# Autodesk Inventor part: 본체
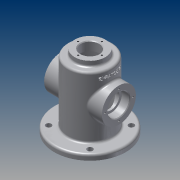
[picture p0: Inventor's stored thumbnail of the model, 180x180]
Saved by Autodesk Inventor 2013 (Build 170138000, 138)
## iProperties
Created: 2014-12
Part Number: 본체
Material: 알루미늄 6061
Document SubType Name: Modeling
Designer: CAD-B28
Density: 2.71 g/cm^3
Mass: 478.821 g
Surface Area: 609.662 cm^2
Volume: 176.687 cm^3
Author: CAD-B28
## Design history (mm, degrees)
sketch "스케치1"
  geometry: C1 r 32.5 at (0, 0); 1 further point
  constraints: 1 centre point, 1 coincident
  dimensions: "d0" = 65 diameter of C1
extrude "돌출1" new body sketch "스케치1" distance "d1" = 43; taper "d3" = 0 deg; dims "d2" = 55, "d4" = 0
sketch "스케치2"
  geometry: C1 r 32.5 at (0, 0) reference; C2 r 52.5 at (0, 0)
  constraints: 1 centre point, 1 coincident
  dimensions: "d5" = 105 diameter of C2
extrude "돌출2" join sketch "스케치2" distance "d6" = 8; taper "d7" = 0 deg
sketch "스케치3"
  geometry: C1 r 52.5 at (0, 0) reference; C2 r 27.5 at (0, 0)
  constraints: 1 centre point, 1 coincident
  dimensions: "d8" = 55 diameter of C2
extrude "돌출3" cut sketch "스케치3" distance "d9" = 93; taper "d10" = 0 deg
sketch "스케치4"
  geometry: L1 (-42.5, 0)-(54.519, 0) reference; L2 (-42.5, 0)-(-42.5, 25); L3 (-42.5, 25)-(42.5, 25); L4 (42.5, 25)-(42.5, 0); L5 (-32.5, -47)-(-32.5, 43) reference; L6 (32.5, -47)-(32.5, 43) reference; 1 further point
  constraints: 8 end point, 3 perpendicular, 2 horizontal, 1 point on line
  dimensions: "d11" = 50 diameter of L3 L1; "d13" = 10 distance between parallel lines of L5 L2; "d14" = 10 distance between parallel lines of L4 L6
revolve "회전1" sketch "스케치4" stored, may be unused: angle "d15" = 90 deg
sketch "스케치5"
  geometry: L1 (-42.66, 0)-(42.5, 0) reference; L2 (-42.66, 0)-(-42.66, 16); L3 (-42.66, 16)-(-30.66, 16); L4 (-30.66, 16)-(-30.66, 12.5); L5 (-30.66, 12.5)-(30.5, 12.5); L6 (30.5, 12.5)-(30.5, 16); L7 (30.5, 16)-(42.5, 16); L8 (42.5, 16)-(42.5, 0); L9 (42.5, -25)-(42.5, 25) reference; 2 further points
  constraints: 16 end point, 4 parallel, 2 horizontal, 2 perpendicular, 1 collinear, 1 midpoint, 1 point on line
  dimensions: "d16" = 12 distance of L2.end L3.end; "d18" = 12 distance of L6.end L7.end; "d19" = 32 diameter of L7 L1; "d21" = 32 diameter of L3 L1; "d22" = 25 diameter of L5 L1
revolve "회전2" sketch "스케치5" stored, may be unused: angle "d23" = 90 deg
extrude "돌출4" cut sketch "스케치3" distance "d24" = 93; taper "d25" = 0 deg
sketch "스케치6"
  geometry: C1 r 32.5 at (0, 0) reference; C2 r 22.5 at (0, 0)
  constraints: 1 centre point, 1 coincident
  dimensions: "d26" = 45 diameter of C2
extrude "돌출5" join sketch "스케치6" distance "d27" = 8; taper "d28" = 0 deg
sketch "스케치7"
  geometry: C1 r 22.5 at (0, 0) reference; C2 r 13.5 at (0, 0)
  constraints: 1 centre point, 1 coincident
  dimensions: "d29" = 27 diameter of C2
extrude "돌출6" cut sketch "스케치7" stored distance "d30" = 8; taper "d31" = 0 deg
sketch "스케치8" dims "d32" = 41
  geometry: L1 (0, 0)-(25, 0); 2 further points
  constraints: 2 end point, 2 horizontal alignment, 1 coincident, 1 horizontal, 1 point on line, 3 other
hole "구멍1" sketch "스케치8" at (20.5, 0) diameter "d33" = 2.459; stored, may be unused: countersink angle "d37" = 90 deg, drill point angle "d39" = 118 deg; dims "d34" = 6, "d35" = 4, "d36" = 2, "d38" = 8
sketch "스케치9" dims "d43" = 35
  geometry: L1 (0, 0)-(0, 20.281); C1 r 22.5 at (0, 0) reference; 1 further point
  constraints: 2 end point, 1 coincident, 1 point on line, 1 vertical, 1 vertical alignment, 2 other
hole "구멍2" sketch "스케치9" at (0, 17.5) diameter "d44" = 2.459; stored, may be unused: countersink angle "d48" = 90 deg, drill point angle "d50" = 118 deg; dims "d45" = 6, "d46" = 4, "d47" = 2, "d49" = 8
chamfer "모따기1" distance "d54" = 1; stored, may be unused: second distance "d55" = 2, angle "d56" = 45 deg
fillet "모깎기1" dims "d57" = 0.3
sketch "스케치10" dims "d58" = 86
  geometry: L1 (0, 0)-(0, 50.353); L2 (0, 0)-(35.191, 35.191); C1 r 52.5 at (0, 0) reference; C2 r 4 at (30.406, 30.406)
  constraints: 4 end point, 1 centre point, 1 coincident, 1 point on line, 1 vertical, 3 other
  dimensions: "d59" = 45 deg angle of L2 L1; "d61" = 8 diameter of C2
extrude "돌출7" cut sketch "스케치10" stored distance "d62" = 8; taper "d63" = 0 deg
fillet "모깎기2" dims "d67" = 3
node "작업 평면1"
sketch "스케치11"
  geometry: L1 (0, 38.927)-(0, 28.211); L2 (-29.5, 43)-(29.5, 43) reference; 2 further points
  constraints: 2 end point, 1 point on line, 1 vertical, 1 other
  dimensions: "d69" = 9 distance from line of L2 point (0, 34)
feature "엠보싱1" sketch "스케치11" dims "d4" = 0, "d11" = 50, "d13" = 10, "d14" = 10, "d70" = 1, "d71" = 0
fillet "모깎기3" dims "d72" = 3
fillet "모깎기4" dims "d73" = 3
node "솔리드1"
pattern_circular "원형 패턴1" dims angle "d41" = 360 deg
mirror "대칭1"
pattern_circular "원형 패턴2" dims angle "d52" = 360 deg
pattern_circular "원형 패턴3" dims angle "d65" = 360 deg
other parameters: "d68" = 35.75
